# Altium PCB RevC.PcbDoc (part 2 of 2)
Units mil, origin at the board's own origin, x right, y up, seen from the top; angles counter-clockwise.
Board outline 3110.24 x 2539.37 mil, 2 copper layers (Top Layer, Bottom Layer); 147 components, 154 nets, 636 pads, 215 vias.
Unrouted connection lines stored in the file: 2.
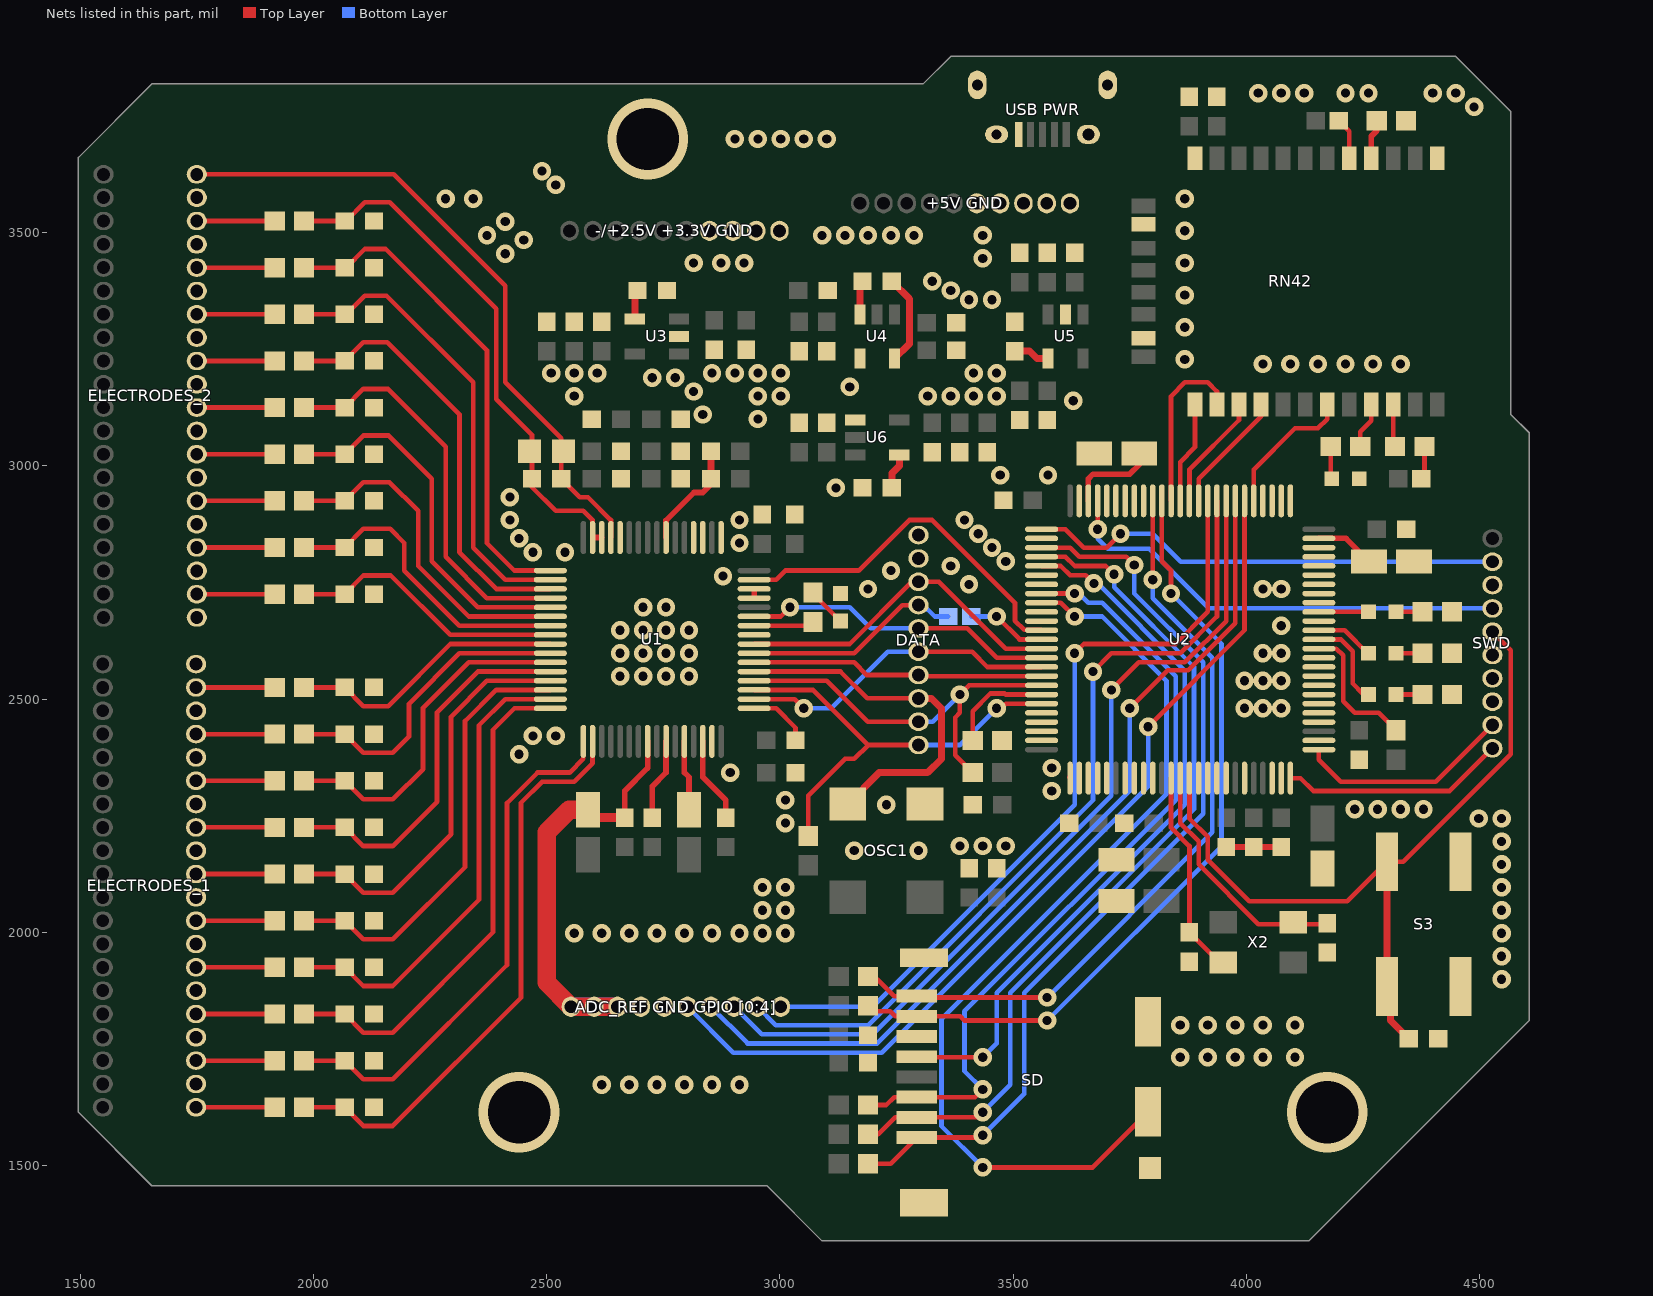
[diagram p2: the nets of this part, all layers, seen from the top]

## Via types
v1: diameter 39.37, hole 19.68, Top Layer to Bottom Layer, 212 vias
v2: diameter 173.23, hole 133.86, Top Layer to Bottom Layer, 3 vias

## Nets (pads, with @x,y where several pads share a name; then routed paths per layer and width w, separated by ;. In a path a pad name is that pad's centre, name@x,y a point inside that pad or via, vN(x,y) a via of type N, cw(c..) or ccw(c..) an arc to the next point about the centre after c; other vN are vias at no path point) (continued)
BIASIN: C1.1 C51.1 R1.2 R23.1 U1.62 U1.63 | length 1153
  Top Layer w10: R1.2@1979.92,3525 C1.1@2066.93,3525 2070.32,3525 2110.32,3565 2163.35,3565 2391.73,3336.61 2391.73,3143.27 2468.5,3066.5 C51.1@2468.5,2972.44 2468.5,2954.72 2519.68,2903.54 2578.74,2903.54 2598.43,2883.86 U1.63@2598.43,2846.46
  Top Layer w12: U1.63@2598.43,2846.46 U1.62@2618.11,2846.46
BIASINV: C51.2 ELECTRODES_2.40 R23.2 U1.61 | length 1404
  Top Layer w10: ELECTRODES_2.40@1750,3625 2172.24,3625 2411.42,3385.83 2411.42,3179.13 2531.5,3059.06 C51.2@2531.5,2972.44 2570.87,2933.07 2588.58,2933.07 2637.8,2883.86 U1.61@2637.8,2846.46
CBIAS: ELECTRODES_2.38 R1.1 | length 168.5
  Top Layer w10: ELECTRODES_2.38@1748.43,3525 ELECTRODES_2.38@1750,3525 R1.1@1916.93,3525
CD_DETECT: SD.9 U2.84 | length 2020.6
  Top Layer w10: v1(3435.04,1496.06) 3670.28,1496.06 SD.9@3789.37,1615.16 ; U2.84@3561.02,2706.69 3602.36,2706.69 v1(3631.89,2677.17)
  Bottom Layer w10: v1(3435.04,1496.06) 3346.3,1584.8 3346.3,1813.48 3828.74,2295.92 3828.74,2539.37 3690.94,2677.17 v1(3631.89,2677.17)
CIN1N: ELECTRODES_1.27 R16.1 | length 168.5
  Top Layer w10: ELECTRODES_1.27@1748.43,1925 R16.1@1916.93,1925
CIN1P: ELECTRODES_1.25 R17.1 | length 168.5
  Top Layer w10: ELECTRODES_1.25@1748.43,1825 R17.1@1916.93,1825
CIN2N: ELECTRODES_1.31 R14.1 | length 168.5
  Top Layer w10: ELECTRODES_1.31@1748.43,2125 R14.1@1916.93,2125
CIN2P: ELECTRODES_1.29 R15.1 | length 168.5
  Top Layer w10: ELECTRODES_1.29@1748.43,2025 R15.1@1916.93,2025
CIN3N: ELECTRODES_1.35 R12.1 | length 168.5
  Top Layer w10: ELECTRODES_1.35@1748.43,2325 R12.1@1916.93,2325
CIN3P: ELECTRODES_1.33 R13.1 | length 168.5
  Top Layer w10: ELECTRODES_1.33@1748.43,2225 R13.1@1916.93,2225
CIN4N: ELECTRODES_1.39 R10.1 | length 168.5
  Top Layer w10: ELECTRODES_1.39@1748.43,2525 R10.1@1916.93,2525
CIN4P: ELECTRODES_1.37 R11.1 | length 168.5
  Top Layer w10: ELECTRODES_1.37@1748.43,2425 R11.1@1916.93,2425
CIN5N: ELECTRODES_2.24 R8.1 | length 168.5
  Top Layer w10: ELECTRODES_2.24@1748.43,2825 ELECTRODES_2.24@1750,2825 R8.1@1916.93,2825
CIN5P: ELECTRODES_2.22 R9.1 | length 168.5
  Top Layer w10: ELECTRODES_2.22@1748.43,2725 ELECTRODES_2.22@1750,2725 R9.1@1916.93,2725
CIN6N: ELECTRODES_2.28 R6.1 | length 168.5
  Top Layer w10: ELECTRODES_2.28@1748.43,3025 ELECTRODES_2.28@1750,3025 R6.1@1916.93,3025
CIN6P: ELECTRODES_2.26 R7.1 | length 168.5
  Top Layer w10: ELECTRODES_2.26@1748.43,2925 ELECTRODES_2.26@1750,2925 R7.1@1916.93,2925
CIN7N: ELECTRODES_2.32 R4.1 | length 168.5
  Top Layer w10: ELECTRODES_2.32@1748.43,3225 ELECTRODES_2.32@1750,3225 R4.1@1916.93,3225
CIN7P: ELECTRODES_2.30 R5.1 | length 168.5
  Top Layer w10: ELECTRODES_2.30@1748.43,3125 ELECTRODES_2.30@1750,3125 R5.1@1916.93,3125
CIN8N: ELECTRODES_2.36 R2.1 | length 168.5
  Top Layer w10: ELECTRODES_2.36@1748.43,3425 ELECTRODES_2.36@1750,3425 R2.1@1916.93,3425
CIN8P: ELECTRODES_2.34 R3.1 | length 168.5
  Top Layer w10: ELECTRODES_2.34@1748.43,3325 ELECTRODES_2.34@1750,3325 R3.1@1916.93,3325
CLK: DATA.3 OSC1.3 U1.37 | length 783.4
  Top Layer w10: U1.37@2944.88,2559.06 3129.92,2559.06 3187.4,2501.57 DATA.3@3297.24,2501.57
  Top Layer w15: OSC1.3@3145.67,2275.2 3212.99,2342.52 3316.93,2342.52 3346.46,2372.05 3346.46,2480.32 3325.2,2501.57 DATA.3@3297.24,2501.57
CS: DATA.7 S4.2 U1.39 | length 486.1
  Top Layer w10: U1.39@2944.88,2598.43 3159.45,2598.43 3262.6,2701.57 DATA.7@3297.24,2701.57
  Bottom Layer w10: DATA.7@3312.01,2706.69 3302.36,2706.69 DATA.7@3297.24,2701.57 3307.28,2701.57 3331.69,2677.17 3361.22,2677.17
CS_1: "ADC_REF GND GPIO [0:4].1" U2.60 | length 1694.4
  Top Layer w10: v1(3631.89,2598.43) 3651.57,2618.11 3848.43,2618.11 3917.32,2687.01 U2.60@3917.32,2925.2
  Bottom Layer w10: 3001.97,1840.55 3198.82,1840.55 3631.89,2273.62 v1(3631.89,2598.43)
CS_2: "ADC_REF GND GPIO [0:4].2" U2.59 | length 1773.7
  Top Layer w10: v1(3671.26,2559.06) 3710.63,2598.43 3858.27,2598.43 3937.01,2677.17 U2.59@3937.01,2925.2
  Bottom Layer w10: 2951.97,1840.55 2991.34,1801.18 3188.98,1801.18 3671.26,2283.46 v1(3671.26,2559.06)
CS_3: "ADC_REF GND GPIO [0:4].3" U2.58 | length 1836.6
  Top Layer w10: v1(3710.63,2519.69) 3769.68,2578.74 3868.11,2578.74 3956.69,2667.32 U2.58@3956.69,2925.2
  Bottom Layer w10: 2901.97,1840.55 2961.02,1781.5 3198.82,1781.5 3710.63,2293.31 v1(3710.63,2519.69)
CS_4: "ADC_REF GND GPIO [0:4].4" U2.57 | length 1896.3
  Top Layer w10: v1(3750,2480.32) 3831.43,2561.74 3875.15,2561.74 3976.38,2662.97 U2.57@3976.38,2925.2
  Bottom Layer w10: 2851.97,1840.55 2930.71,1761.81 3208.66,1761.81 3750,2303.15 v1(3750,2480.32)
CS_5: "ADC_REF GND GPIO [0:4].5" U2.56 | length 1962.5
  Top Layer w10: v1(3789.37,2440.94) 3996.06,2647.64 U2.56@3996.06,2925.2
  Bottom Layer w10: 2801.97,1840.55 2900.39,1742.13 3218.5,1742.13 3789.37,2312.99 v1(3789.37,2440.94)
CSRB1: ELECTRODES_1.23 R18.1 | length 168.5
  Top Layer w10: ELECTRODES_1.23@1748.43,1725 R18.1@1916.93,1725
CSRB2: ELECTRODES_1.21 R19.1 | length 168.5
  Top Layer w10: ELECTRODES_1.21@1748.43,1625 R19.1@1916.93,1625
DIN: DATA.5 U1.34 U2.91 | length 688.1
  Top Layer w10: U1.34@2944.88,2500 3031.5,2500 v1(3051.18,2480.32) ; DATA.5@3297.24,2601.57 3412.2,2601.57 3444.88,2568.9 U2.91@3561.02,2568.9
  Bottom Layer w10: v1(3051.18,2480.32) 3110.24,2480.32 3231.5,2601.57 DATA.5@3297.24,2601.57
DOUT: DATA.6 U1.43 U2.90 | length 669.1
  Top Layer w10: U1.43@2944.88,2677.17 3001.97,2677.17 v1(3021.65,2696.85) ; DATA.6@3297.24,2651.57 3401.57,2651.57 3464.57,2588.58 U2.90@3561.02,2588.58
  Bottom Layer w10: v1(3021.65,2696.85) 3149.61,2696.85 3194.88,2651.57 DATA.6@3297.24,2651.57
DRDY: U1.47 U2.87 | length 789.6
  Top Layer w10: U1.47@2944.88,2755.91 2992.13,2755.91 3011.81,2775.59 3169.29,2775.59 3277.56,2883.86 3326.77,2883.86 3503.94,2706.69 3503.94,2668.15 3523.67,2648.42 3560.24,2648.42 U2.87@3561.02,2647.64
GND: "+5V GND.6" "+5V GND.7" "+5V GND.8" "+5V GND.9" "+5V GND.10" "-/+2.5V +3.3V GND.7" "-/+2.5V +3.3V GND.8" "-/+2.5V +3.3V GND.9" "-/+2.5V +3.3V GND.10" "ADC_REF GND GPIO [0:4].6" "ADC_REF GND GPIO [0:4].7" "USB PWR.5" "USB PWR.6" C1.2 C2.2 C3.2 C4.2 C5.2 C6.2 C7.2 C8.2 C9.2 C10.2 C11.2 C12.2 C13.2 C14.2 C15.2 C16.2 C17.2 C18.2 C19.2 C20.1 C21.1 C22.1 C23.1 C24.1 C26.2 C27.2 C28.1 C29.1 C30.1 C31.1 C32.1 C33.1 C34.1 C35.1 C36.2 C37.2 C38.1 C39.1 C40.1 C41.2 C42.1 C43.1 C44.1 C45.1 C46.1 C47.2 C48.2 C49.2 C52.2 C53.2 C55.1 C56.1 C57.1 C58.1 C59.2 C60.2 C61.1 C62.2 C63.2 C64.1 C67.2 C71.1 C72.1 C73.1 C74.1 C75.1 C76.2 C77.1 C78.1 C79.2 C80.2 C81.2 C82.2 C83.2 C84.2 DATA.9 DATA.10 ELECTRODES_1.22 ELECTRODES_1.24 ELECTRODES_1.26 ELECTRODES_1.28 ELECTRODES_1.30 ELECTRODES_1.32 ELECTRODES_1.34 ELECTRODES_1.36 ELECTRODES_1.38 ELECTRODES_1.40 ELECTRODES_2.21 ELECTRODES_2.23 ELECTRODES_2.25 ELECTRODES_2.27 ELECTRODES_2.29 ELECTRODES_2.31 ELECTRODES_2.33 ELECTRODES_2.35 ELECTRODES_2.37 ELECTRODES_2.39 LED1.2 LED5.2 OSC1.2 R20.2 R25.2 R26.2 R27.2 R29.1 RN42.1 RN42.12 RN42.28 RN42.29 S3.B SD.6 SWD.3 SWD.6 SWD.7 SWD.8 U1.31 U1.33 U1.41 U1.45 U1.46 U1.49 U1.51 U1.52 U1.60 U2.10 U2.20 U2.27 U2.74 U2.99 U3.2 U4.4 U5.2 U6.1 | length 283.4
  Top Layer w10: U1.51@2833.74,2841.19 2833.74,2846.46 U1.51@2834.65,2846.46 ; U1.33@2944.88,2480.32 2992.13,2480.32 3033.46,2438.98 C62.2@3033.46,2411.42
  Top Layer w12: v1@2887.51,2342.52 v1(2893.7,2342.52) ; U1.45@2944.88,2716.54 U1.46@2944.88,2736.22 ; C71.1@3956.69,2183.07 C72.1@4015.75,2183.07 C73.1@4074.8,2183.07
  other v1: 2618.11,1673.23 2677.17,1673.23 2736.22,1673.23 2795.28,1673.23 2854.33,1673.23 2913.39,1673.23 3858.27,1732.28 3917.32,1732.28 3976.38,1732.28 4035.43,1732.28 4104.33,1732.28 3858.27,1801.18 3917.32,1801.18 3976.38,1801.18 4035.43,1801.18 4104.33,1801.18 4547.24,1899.61 4547.24,1948.82 2559.06,1998.03 2618.11,1998.03 2677.17,1998.03 2736.22,1998.03 2795.28,1998.03 2854.33,1998.03 2913.39,1998.03 2962.6,1998.03 3011.81,1998.03 4547.24,1998.03 2962.6,2047.24 3011.81,2047.24 4547.24,2047.24 2962.6,2096.46 3011.81,2096.46 4547.24,2096.46 4547.24,2145.67 3159.45,2175.2 3297.24,2175.2 3385.83,2185.04 3435.04,2185.04 3484.25,2185.04 4547.24,2194.88 3011.81,2234.25 4498.03,2244.09 4547.24,2244.09 4232.28,2263.78 4281.5,2263.78 4330.71,2263.78 4379.92,2263.78 3228.35,2273.62 3011.81,2283.46 3582.68,2303.15 3582.68,2352.36 2440.94,2381.89 2470.47,2421.26 2519.68,2421.26 3996.06,2480.32 4035.43,2480.32 4074.8,2480.32 3996.06,2539.37 4035.43,2539.37 4074.8,2539.37 2657.48,2549.21 2706.69,2549.21 2755.91,2549.21 2805.12,2549.21 2657.48,2598.43 2706.69,2598.43 2755.91,2598.43 2805.12,2598.43 4035.43,2598.43 4074.8,2598.43 2657.48,2647.64 2706.69,2647.64 2755.91,2647.64 2805.12,2647.64 4074.8,2657.48 2706.69,2696.85 2755.91,2696.85 3188.98,2736.22 4035.43,2736.22 4074.8,2736.22 3405.51,2746.06 2877.95,2763.78 3238.19,2775.59 3366.14,2785.43 3484.25,2795.28 2470.47,2814.96 2539.37,2814.96 3454.72,2824.8 2913.39,2834.65 2440.94,2844.49 3425.2,2854.33 2421.26,2883.86 2913.39,2883.86 3395.67,2883.86 2421.26,2933.07 3120.08,2952.76 3472.44,2980.32 3574.8,2980.32 2952.76,3100.39 2834.65,3110.24 3628.94,3139.76 2559.06,3149.61 2952.76,3149.61 3001.97,3149.61 3316.93,3149.61 3366.14,3149.61 3415.35,3149.61 3464.57,3149.61 2814.96,3159.45 3149.61,3169.29 2726.38,3188.98 2775.59,3188.98 2509.84,3198.82 2559.06,3198.82 2608.27,3198.82 2854.33,3198.82 2903.54,3198.82 2952.76,3198.82 3001.97,3198.82 3415.35,3198.82 3464.57,3198.82 4035.43,3218.5 4094.49,3218.5 4153.54,3218.5 4212.6,3218.5 4271.65,3218.5 4330.71,3218.5 3868.11,3228.35 3868.11,3297.24 3405.51,3356.3 3454.72,3356.3 3868.11,3366.14 3366.14,3375.98 3326.77,3395.67 2814.96,3435.04 2874.02,3435.04 2923.23,3435.04 3868.11,3435.04 3435.04,3444.88 2411.42,3454.72 2450.79,3484.25 2372.05,3494.09 3090.55,3494.09 3139.76,3494.09 3188.98,3494.09 3238.19,3494.09 3287.4,3494.09 3435.04,3494.09 3868.11,3503.94 2411.42,3523.62 2283.46,3572.83 2342.52,3572.83 3868.11,3572.83 2519.68,3602.36 2490.16,3631.89 2903.54,3700.79 2952.76,3700.79 3001.97,3700.79 3051.18,3700.79 3100.39,3700.79 4488.19,3769.68 4025.59,3799.21 4074.8,3799.21 4124.02,3799.21 4212.6,3799.21 4261.81,3799.21 4399.61,3799.21 4448.82,3799.21
  other v2: 2440.94,1614.17 4173.23,1614.17 2716.54,3700.79
IN1N: C16.1 R16.2 U1.15 | length 1018.1
  Top Layer w10: R16.2@1979.92,1925 C16.1@2066.93,1925 2106.93,1885 2170,1885 2355,2070 2355,2443.58 2411.42,2500 U1.15@2507.87,2500
IN1P: C17.1 R17.2 U1.16 | length 1086.9
  Top Layer w10: R17.2@1979.92,1825 C17.1@2066.93,1825 2106.93,1785 2170,1785 2385,2000 2385,2434.21 2431.1,2480.32 U1.16@2507.87,2480.32
IN2N: C14.1 R14.2 U1.13 | length 880.5
  Top Layer w10: R14.2@1979.92,2125 C14.1@2066.93,2125 2106.93,2085 2170,2085 2295,2210 2295,2462.32 2372.05,2539.37 U1.13@2507.87,2539.37
IN2P: C15.1 R15.2 U1.14 | length 949.3
  Top Layer w10: R15.2@1979.92,2025 C15.1@2066.93,2025 2106.93,1985 2170,1985 2325,2140 2325,2452.95 2391.73,2519.68 U1.14@2507.87,2519.68
IN3N: C12.1 R12.2 U1.11 | length 743
  Top Layer w10: R12.2@1979.92,2325 C12.1@2066.93,2325 2106.93,2285 2170,2285 2235,2350 2235,2481.06 2332.68,2578.74 U1.11@2507.87,2578.74
IN3P: C13.1 R13.2 U1.12 | length 811.8
  Top Layer w10: R13.2@1979.92,2225 C13.1@2066.93,2225 2106.93,2185 2170,2185 2265,2280 2265,2471.69 2352.36,2559.06 U1.12@2507.87,2559.06
IN4N: C10.1 R10.2 U1.9 | length 599.7
  Top Layer w10: R10.2@1979.92,2525 C10.1@2066.93,2525 2106.93,2485 2160.2,2485 2293.31,2618.11 U1.9@2507.87,2618.11
IN4P: C11.1 R11.2 U1.10 | length 674.2
  Top Layer w10: R11.2@1979.92,2425 C11.1@2066.93,2425 2106.93,2385 2170,2385 2205,2420 2205,2490.43 2312.99,2598.43 U1.10@2507.87,2598.43
IN5N: C8.1 R8.2 U1.7 | length 665.1
  Top Layer w10: R8.2@1979.92,2825 C8.1@2066.93,2825 2106.93,2865 2164.53,2865 2194.88,2834.65 2194.88,2775.59 2312.99,2657.48 U1.7@2507.87,2657.48
IN5P: C9.1 R9.2 U1.8 | length 597.2
  Top Layer w10: R9.2@1979.92,2725 C9.1@2066.93,2725 2106.93,2765 2166.1,2765 2293.31,2637.8 U1.8@2507.87,2637.8
IN6N: C6.1 R6.2 U1.5 | length 800.8
  Top Layer w10: R6.2@1979.92,3025 C6.1@2066.93,3025 2106.93,3065 2161.38,3065 2253.94,2972.44 2253.94,2795.28 2352.36,2696.85 U1.5@2507.87,2696.85
IN6P: C7.1 R7.2 U1.6 | length 732.9
  Top Layer w10: R7.2@1979.92,2925 C7.1@2066.93,2925 2106.93,2965 2162.95,2965 2224.41,2903.54 2224.41,2785.43 2332.68,2677.17 U1.6@2507.87,2677.17
IN7N: C4.1 R4.2 U1.3 | length 936.5
  Top Layer w10: R4.2@1979.92,3225 C4.1@2066.93,3225 2106.93,3265 2158.23,3265 2312.99,3110.24 2312.99,2814.96 2391.73,2736.22 U1.3@2507.87,2736.22
IN7P: C5.1 R5.2 U1.4 | length 868.7
  Top Layer w10: R5.2@1979.92,3125 C5.1@2066.93,3125 2106.93,3165 2159.8,3165 2283.46,3041.34 2283.46,2805.12 2372.05,2716.54 U1.4@2507.87,2716.54
IN8N: C2.1 R2.2 U1.1 | length 1072.2
  Top Layer w10: R2.2@1979.92,3425 C2.1@2066.93,3425 2070.32,3425 2110.32,3465 2155.08,3465 2372.05,3248.03 2372.05,2834.65 2431.1,2775.59 U1.1@2507.87,2775.59
IN8P: C3.1 R3.2 U1.2 | length 1004.4
  Top Layer w10: R3.2@1979.92,3325 C3.1@2066.93,3325 2070.32,3325 2110.32,3365 2156.65,3365 2342.52,3179.13 2342.52,2824.8 2411.42,2755.91 U1.2@2507.87,2755.91
NetC25_1: C25.1 U4.3 | length 73.3
  Top Layer w15: U4.3@3171.26,3324.8 3171.26,3389.76 C25.1@3177.17,3395.67
NetC25_2: C25.2 U4.5 | length 193.9
  Top Layer w15: C25.2@3240.16,3395.67 3277.56,3358.27 3277.56,3261.81 U4.5@3246.06,3230.32
NetC27_1: C27.1 U3.4 | length 61
  Top Layer w15: U3.4@2688.98,3314.96 C27.1@2688.98,3375.98
NetC32_2: C32.2 U5.4 | length 77.4
  Top Layer w15: C32.2@3503.94,3246.06 3535.43,3246.06 3551.18,3230.32 U5.4@3574.8,3230.32
NetC47_1: C47.1 U2.73 | length 192.8
  Top Layer w12: U2.73@3661.42,2925.2 3661.42,2972.44 3671.26,2982.28 3750,2982.28 3770.54,3002.83 C47.1@3770.54,3026.65
NetC50_1: C50.1 C54.1 U1.55 | length 236
  Top Layer w12: U1.55@2755.91,2846.46 2755.91,2883.04 2815.78,2942.91 2834.65,2942.91 2852.36,2960.63 C54.1@2852.36,2972.44
  Top Layer w15: C54.1@2852.36,2972.44 C50.1@2852.36,3031.5
NetC55_2: C55.2 U6.4 | length 77.4
  Top Layer w15: C55.2@3240.16,2952.76 3240.16,2984.25 3255.91,3000 U6.4@3255.91,3023.62
NetC60_1: C60.1 U2.49 | length 127.7
  Top Layer w12: U2.49@4155.51,2844.49 4213.58,2844.49 C60.1@4262.8,2795.28
NetC66_1: C66.1 U1.28 | length 154.7
  Top Layer w12: U1.28@2795.28,2409.45 2795.28,2342.52 2805.12,2332.68 C66.1@2805.12,2262.8 C66.1@2805.12,2258.86
NetC69_1: C69.1 U1.26 | length 175.6
  Top Layer w12: C69.1@2726.38,2246.06 2726.38,2312.99 2755.91,2342.52 U1.26@2755.91,2409.45
NetC70_1: C70.1 U1.30 | length 183.8
  Top Layer w12: U1.30@2834.65,2409.45 2834.65,2332.68 2883.86,2283.46 C70.1@2883.86,2246.06
NetC80_1: C80.1 U2.13 X2.1 | length 522.5
  Top Layer w10: U2.13@3858.27,2330.71 3858.27,2234.25 3897.64,2194.88 3897.64,2145.67 4025.59,2017.72 4157.48,2017.72 C80.1@4163.39,2023.62
NetC81_1: C81.1 U2.12 X2.3 | length 440.2
  Top Layer w10: U2.12@3838.58,2330.71 3838.58,2224.41 3877.95,2185.04 C81.1@3877.95,2009.84 ; C81.1@3868.11,2009.84 X2.3@3940.94,1937.01
NetLED1_1: LED1.1 R24.2 | length 71
  Top Layer w10: R24.2@3069.88,2727.36 LED1.1@3120.08,2677.17
NetLED2_2: LED2.2 R25.1 | length 57.1
  Top Layer w10: LED2.2@4311.02,2687.01 LED2.2@4320.87,2687.01 R25.1@4368.11,2687.01
NetLED3_2: LED3.2 R26.1 | length 57.1
  Top Layer w10: LED3.2@4311.02,2598.43 LED3.2@4320.87,2598.43 R26.1@4368.11,2598.43
NetLED4_2: LED4.2 R27.1 | length 57.1
  Top Layer w10: LED4.2@4311.02,2509.84 LED4.2@4320.87,2509.84 R27.1@4368.11,2509.84
NetLED5_1: LED5.1 R21.1 | length 73.7
  Top Layer w10: R21.1@4181.1,3041.34 4181.1,2970.47 LED5.1@4183.07,2972.44
NetR20_1: R20.1 RN42.4 | length 85.6
  Top Layer w12: RN42.4@4267.72,3659.45 4267.72,3706.69 4279.53,3718.5 R20.1@4279.53,3740.16
NetR21_2: R21.2 RN42.21 | length 100.3
  Top Layer w10: R21.2@4244.09,3041.34 4244.09,3072.83 4267.72,3096.46 RN42.21@4267.72,3131.89
NetR22_1: R22.1 RN42.22 | length 92.2
  Top Layer w10: RN42.22@4314.96,3131.89 4314.96,3045.28 R22.1@4318.9,3041.34
NetR22_2: R22.2 S2.1 | length 71.8
  Top Layer w10: S2.1@4375,2972.44 4381.89,2979.33 R22.2@4381.89,3041.34
NetR24_1: R24.1 U1.42 | length 129.2
  Top Layer w10: U1.42@2944.88,2657.48 3062.99,2657.48 R24.1@3070.87,2665.35
NetR29_2: R29.2 U2.94 | length 226.8
  Top Layer w10: R29.2@3413.39,2411.42 3413.39,2473.94 3451.44,2512 3482.09,2512 3484.25,2509.84 U2.94@3561.02,2509.84
NetRN42_5: RN42.5 S1.2 | length 90.1
  Top Layer w10: S1.2@4197.83,3740.16 4220.47,3717.52 RN42.5@4220.47,3659.45
NRST: C83.1 S3.A SWD.5 U2.14 | length 1686.7
  Top Layer w10: U2.14@3877.95,2330.71 3877.95,2244.09 3917.32,2204.72 3917.32,2155.51 4005.91,2066.93 4216.54,2066.93 S3.A@4301.18,2151.57 4336.61,2151.57 4566.93,2381.89 4566.93,2605.12 SWD.5@4527.56,2644.49
  Top Layer w15: S3.A@4301.18,2151.57 S3.A@4301.18,1883.86 4309.06,1875.98 4309.06,1811.02 C83.1@4348.43,1771.65
PA0: U2.23
PA1: U2.24
PA4: U2.29
PA5: U2.30
PA6: U2.31
PA7: U2.32
PA8: U2.67
PA9: U2.68
PA10: U2.69
PA11: U2.70
PA12: U2.71
PA15: U2.77
PB0: U2.35
PB1: U2.36
PB2: R28.2 U2.37 | length 295.6
  Top Layer w10: U2.37@4155.51,2608.27 4192.91,2608.27 4207.44,2593.74 4207.44,2495.32 4232.28,2470.47 4283.46,2470.47 R28.2@4320.87,2433.07
PB3: DATA.8 U1.40 U2.89 | length 730.8
  Top Layer w10: U1.40@2944.88,2618.11 3149.61,2618.11 3283.07,2751.57 DATA.8@3297.24,2751.57 3340.94,2751.57 3484.25,2608.27 U2.89@3561.02,2608.27
PB6: DATA.4 U1.38 U2.92 | length 628.4
  Top Layer w10: U1.38@2944.88,2578.74 3159.45,2578.74 3186.61,2551.57 DATA.4@3297.24,2551.57 3299.61,2549.21 U2.92@3561.02,2549.21
PB7: DATA.2 R36.1 U1.36 U2.93 | length 871.7
  Top Layer w10: U1.36@2944.88,2539.37 3100.39,2539.37 3188.19,2451.57 DATA.2@3297.24,2451.57 ; R36.1@3413.39,2342.52 3375.98,2379.92 3375.98,2460.63 3385.83,2470.47 v1(3385.83,2509.84) 3405.51,2529.53 U2.93@3561.02,2529.53
  Bottom Layer w10: DATA.2@3297.24,2451.57 3327.56,2451.57 v1(3385.83,2509.84)
PB8: DATA.1 R37.1 U1.35 U2.95 | length 961.2
  Top Layer w10: U1.35@2944.88,2519.68 3070.87,2519.68 3188.98,2401.57 ; R37.1@3061.02,2206.69 3061.02,2293.31 3139.76,2372.05 3159.45,2372.05 3188.98,2401.57 ; DATA.1@3297.24,2401.57 3188.98,2401.57 ; v1(3464.57,2480.32) 3474.41,2480.32 3484.25,2490.16 U2.95@3561.02,2490.16
  Bottom Layer w10: DATA.1@3297.24,2401.57 3385.83,2401.57 v1(3464.57,2480.32)
PB9: U2.96
PB10: U2.47
PB11: U2.48
PB12: U2.51
PB13: U2.52
PB14: U2.53
PB15: U2.54
PC0: U2.15
PC1: U2.16
PC2: U2.17
PC3: U2.18
PC4: U2.33
PC5: U2.34
PC13: U2.7
PC14: U2.8
PC15: U2.9
PD0: U2.81
PD1: U2.82
PD4: U2.85
PD5: U2.86
PD7: S4.1 U2.88 | length 171
  Top Layer w10: v1(3464.57,2677.17) 3513.78,2627.95 U2.88@3561.02,2627.95
  Bottom Layer w10: 3410.43,2677.17 v1(3464.57,2677.17)
PE0: U2.97
PE1: U2.98
PE2: U2.1 | length 2.8
  Top Layer w10: U2.1@3620.08,2332.68 U2.1@3622.05,2330.71
PE3: U2.2
PE4: U2.3
PE5: U2.4
PE6: U2.5
PE7: LED4.1 U2.38 | length 192.8
  Top Layer w10: U2.38@4155.51,2627.95 4202.76,2627.95 4228.35,2602.36 4228.35,2533.46 4250,2511.81 LED4.1@4259.84,2511.81
PE8: LED3.1 U2.39 | length 126.1
  Top Layer w10: U2.39@4155.51,2647.64 4210.63,2647.64 LED3.1@4260.83,2597.44
PE9: U2.40
PE10: LED2.1 U2.41 | length 106.3
  Top Layer w10: U2.41@4155.51,2687.01 LED2.1@4261.81,2687.01
PE11: U2.42
PE12: U2.43
PE13: U2.44
PE14: U2.45
PE15: U2.46
RN42_CTS: RN42.16 U2.61 | length 262.1
  Top Layer w10: U2.61@3897.64,2925.2 3897.64,2972.44 4031.5,3106.3 RN42.16@4031.5,3131.89
RN42_RTS: RN42.15 U2.62 | length 250.7
  Top Layer w10: U2.62@3877.95,2925.2 3877.95,2992.13 3984.25,3098.43 RN42.15@3984.25,3131.89
RN42_STATUS: RN42.19 U2.55 | length 300.8
  Top Layer w10: U2.55@4015.75,2925.2 4015.75,2992.13 4104.33,3080.71 4153.54,3080.71 4173.23,3100.39 RN42.19@4173.23,3131.89
SDIO_CLK: SD.5 U2.80 | length 1542.4
  Top Layer w10: SD.5@3293.31,1733.27 3294.29,1732.28 v1(3435.04,1732.28) ; U2.80@3561.02,2785.43 3602.36,2785.43 3622.05,2765.75 3655.51,2765.75 v1(3673.23,2748.03)
  Bottom Layer w10: v1(3435.04,1732.28) 3464.57,1761.81 3464.57,1870.08 3868.11,2273.62 3868.11,2561.02 v1@3681.1,2748.03
SDIO_CMD: R32.2 SD.3 U2.83 | length 1708.4
  Top Layer w10: R32.2@3190.94,1629.92 3228.35,1629.92 3245.08,1646.65 SD.3@3293.31,1646.65 3418.31,1646.65 v1(3435.04,1663.39) ; U2.83@3561.02,2726.38 v1(3631.89,2726.38)
  Bottom Layer w10: v1(3435.04,1663.39) 3395.67,1702.76 3395.67,1830.71 3848.43,2283.46 3848.43,2549.21 3690.94,2706.69 3661.42,2706.69 3641.73,2726.38 v1(3631.89,2726.38)
SDIO_D0: R31.2 SD.7 U2.65 | length 1712.1
  Top Layer w10: R31.2@3190.94,1830.71 3236.22,1830.71 3247.05,1819.88 SD.7@3293.31,1819.88 3386.81,1819.88 3395.67,1811.02 v1(3572.83,1811.02) ; U2.65@3818.9,2925.2 3818.9,2795.28 3838.58,2775.59 v1(3838.58,2726.38)
  Bottom Layer w10: v1(3572.83,1811.02) 3946.85,2185.04 3946.85,2618.11 v1(3838.58,2726.38)
SDIO_D1: R30.2 SD.8 U2.66 | length 1662.9
  Top Layer w10: R30.2@3190.94,1899.61 3208.66,1899.61 3245.08,1863.19 SD.8@3293.31,1863.19 3296.26,1860.24 v1(3572.83,1860.24) ; v1(3799.21,2755.91) U2.66@3799.21,2925.2
  Bottom Layer w10: v1(3572.83,1860.24) 3927.17,2214.57 3927.17,2588.58 3799.21,2716.54 v1(3799.21,2755.91)
SDIO_D2: R34.2 SD.1 U2.78 | length 1964.9
  Top Layer w10: R34.2@3188.98,1503.94 3237.2,1503.94 SD.1@3293.31,1560.04 3430.12,1560.04 v1(3435.04,1564.96) ; U2.78@3561.02,2824.8 3622.05,2824.8 3641.73,2805.12 3742.13,2805.12 v1(3759.84,2787.4)
  Bottom Layer w10: v1(3435.04,1564.96) 3523.62,1653.54 3523.62,1870.08 3907.48,2253.94 3907.48,2578.74 3759.84,2726.38 v1(3759.84,2787.4)
SDIO_D3: R33.2 SD.2 U2.79 | length 1848.7
  Top Layer w10: R33.2@3188.98,1566.93 3210.63,1566.93 3247.05,1603.35 SD.2@3293.31,1603.35 3424.21,1603.35 v1(3435.04,1614.17) ; U2.79@3561.02,2805.12 3612.2,2805.12 3631.89,2785.43 3698.82,2785.43 v1(3716.54,2767.72)
  Bottom Layer w10: v1(3435.04,1614.17) 3494.09,1673.23 3494.09,1870.08 3887.8,2263.78 3887.8,2568.9 3716.54,2740.16 v1(3716.54,2767.72)
SRB1: C18.1 R18.2 U1.17 | length 1140.8
  Top Layer w10: R18.2@1979.92,1725 C18.1@2066.93,1725 2106.93,1685 2170,1685 2415,1930 2415,2277.2 2480.32,2342.52 2549.21,2342.52 2578.74,2372.05 U1.17@2578.74,2409.45
SRB2: C19.1 R19.2 U1.18 | length 1248.9
  Top Layer w10: R19.2@1979.92,1625 C19.1@2066.93,1625 2106.93,1585 2170,1585 2445,1860 2445,2277.68 2490.16,2322.83 2559.06,2322.83 2598.43,2362.2 U1.18@2598.43,2409.45
SWCLK: SWD.2 U2.76 | length 1019.9
  Top Layer w10: U2.76@3561.02,2864.17 3612.2,2864.17 3651.57,2824.8 3700.79,2824.8 v1(3730.32,2854.33)
  Bottom Layer w10: v1(3730.32,2854.33) 3799.21,2854.33 3859.06,2794.49 SWD.2@4527.56,2794.49
SWDIO: SWD.4 U2.72 | length 989.4
  Top Layer w10: v1(3681.1,2864.17) U2.72@3681.1,2925.2
  Bottom Layer w10: v1(3681.1,2864.17) 3681.1,2844.25 3702.7,2822.65 3791.53,2822.65 3919.68,2694.49 SWD.4@4527.56,2694.49
USART6_RX: RN42.14 U2.64 | length 370.8
  Top Layer w10: U2.64@3838.58,2925.2 3838.58,3149.61 3868.11,3179.13 3917.32,3179.13 3937.01,3159.45 RN42.14@3937.01,3131.89
USART6_TX: RN42.13 U2.63 | length 219.7
  Top Layer w10: U2.63@3858.27,2925.2 3858.27,3008.27 3889.76,3039.76 RN42.13@3889.76,3131.89
USART_RX: SWD.9 U2.26 | length 459.6
  Top Layer w10: U2.26@4155.51,2391.73 4155.51,2370.08 4202.76,2322.83 4405.91,2322.83 4517.72,2434.65 SWD.9@4517.72,2444.49
USART_TX: SWD.10 U2.25 | length 478.2
  Top Layer w10: U2.25@4094.49,2330.71 4116.14,2330.71 4143.7,2303.15 4436.22,2303.15 4517.72,2384.65 SWD.10@4517.72,2394.49
VREFP: "ADC_REF GND GPIO [0:4].8" "ADC_REF GND GPIO [0:4].9" "ADC_REF GND GPIO [0:4].10" C65.1 C68.1 U1.24 | length 973.5
  Top Layer w12: C68.1@2667.32,2246.06 2667.32,2303.15 2716.54,2352.36 U1.24@2716.54,2409.45
  Top Layer w20: C65.1@2588.58,2262.8 2605.31,2246.06 C68.1@2667.32,2246.06
  Top Layer w40: C65.1@2588.58,2262.8 2548.23,2262.8 2500,2214.57 2500,1892.52 2551.97,1840.55 2601.97,1840.55 2651.97,1840.55
  Bottom Layer w40: 2551.97,1840.55 2601.97,1840.55 2651.97,1840.55
pads on no net: "USB PWR.2" "USB PWR.3" "USB PWR.4" RN42.2 RN42.3 RN42.6 RN42.7 RN42.8 RN42.9 RN42.10 RN42.17 RN42.18 RN42.20 RN42.23 RN42.24 RN42.30 RN42.31 RN42.32 RN42.33 RN42.34 RN42.35 U1.27 U1.29 U1.44 U1.64 X2.2 X2.4

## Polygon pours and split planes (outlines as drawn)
GND on Bottom Layer "GND" (solid, remove dead copper, shelved, pour order 3): 4602.5,1860.9 4602.5,1338.58 1496.06,1338.58 1496.06,3877.95 4602.5,3877.95 4602.5,2530.19
GND on Top Layer "GND" (solid, remove dead copper, shelved, pour order 4): 4602.36,1338.58 3464.57,1338.58 1496.06,1338.58 1496.06,3602.36 1496.06,3877.95 4602.36,3877.95

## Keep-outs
Keep-Out Layer:
  lines w8: 1496.06,1614.17 1496.06,3661.42 1653.54,3818.9 3307.09,3818.9 3366.14,3877.95 4448.82,3877.95 4566.93,3759.84 4566.93,3110.24 4606.3,3070.87 4606.3,1811.02 4133.86,1338.58 3090.55,1338.58 2972.44,1456.69 2490.16,1456.69 1653.54,1456.69 1496.06,1614.17

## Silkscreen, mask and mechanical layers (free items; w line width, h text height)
Top Overlay:
  text "BIASINV" at 2180,3610 h30
  text "BIASIN" at 2180,3510 h30
  text "IN8N" at 2180,3410 h30
  text "IN8P" at 2180,3310 h30
  text "IN7N" at 2180,3210 h30
  text "IN7P" at 2180,3110 h30
  text "IN6N" at 2180,3010 h30
  text "IN6P" at 2180,2910 h30
  text "IN5N" at 2180,2810 h30
  text "IN5P" at 2180,2710 h30
  text "IN4N" at 2180,2510 h30
  text "IN4P" at 2180,2410 h30
  text "IN3N" at 2180,2310 h30
  text "IN3P" at 2180,2210 h30
  text "IN2N" at 2180,2110 h30
  text "IN2P" at 2180,2010 h30
  text "IN1N" at 2180,1910 h30
  text "IN1P" at 2180,1810 h30
  text "SRB1" at 2180,1710 h30
  text "SRB2" at 2180,1610 h30
Bottom Overlay:
  lines w8: 3740.16,3661.42 4409.45,3661.42
  text "BioEXG Rev.C" at 4409.45,3681.1 h60
  text "5/10/2014" at 4370.08,3582.68 h40
  text "Jae Choi" at 4370.08,3503.94 h40
Mechanical 2:
  lines w8: 1496.06,1614.17 1496.06,3661.42 1653.54,3818.9 3307.09,3818.9 3366.14,3877.95 4448.82,3877.95 4566.93,3759.84 4566.93,3110.24 4606.3,3070.87 4606.3,1811.02 4133.86,1338.58 3090.55,1338.58 2972.44,1456.69 2490.16,1456.69 1653.54,1456.69 1496.06,1614.17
